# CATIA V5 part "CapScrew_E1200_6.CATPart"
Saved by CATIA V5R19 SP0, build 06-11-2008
Part number: CapScrew_E1200_6
Nomenclature: E 1200/6x30
Source: Unknown
Description: MEUSBURGER
Bounding box of the stored display mesh (mm): x -4.991 to 4.998, y -5 to 5, z 0 to 36
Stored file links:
  C:\Users\jsmid\Desktop\DP_Smidak_Forma LEGO\CapScrew_E1200_6.CATPart
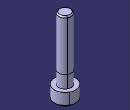
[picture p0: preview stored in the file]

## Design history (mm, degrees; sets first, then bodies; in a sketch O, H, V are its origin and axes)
Body1 (main body)
  Solid1 "PartBody": solid without history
